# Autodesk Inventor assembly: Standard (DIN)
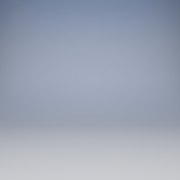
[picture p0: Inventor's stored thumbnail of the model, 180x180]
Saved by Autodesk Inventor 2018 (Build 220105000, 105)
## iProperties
Created: 2017-02
Part Number: Standard (DIN)
Material: Ogólny
Document SubType Name: Assembly
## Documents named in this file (1)
- C:\Users\Joffi\Desktop\Templates.Base\Metric.Base\Standard (DIN).iam
